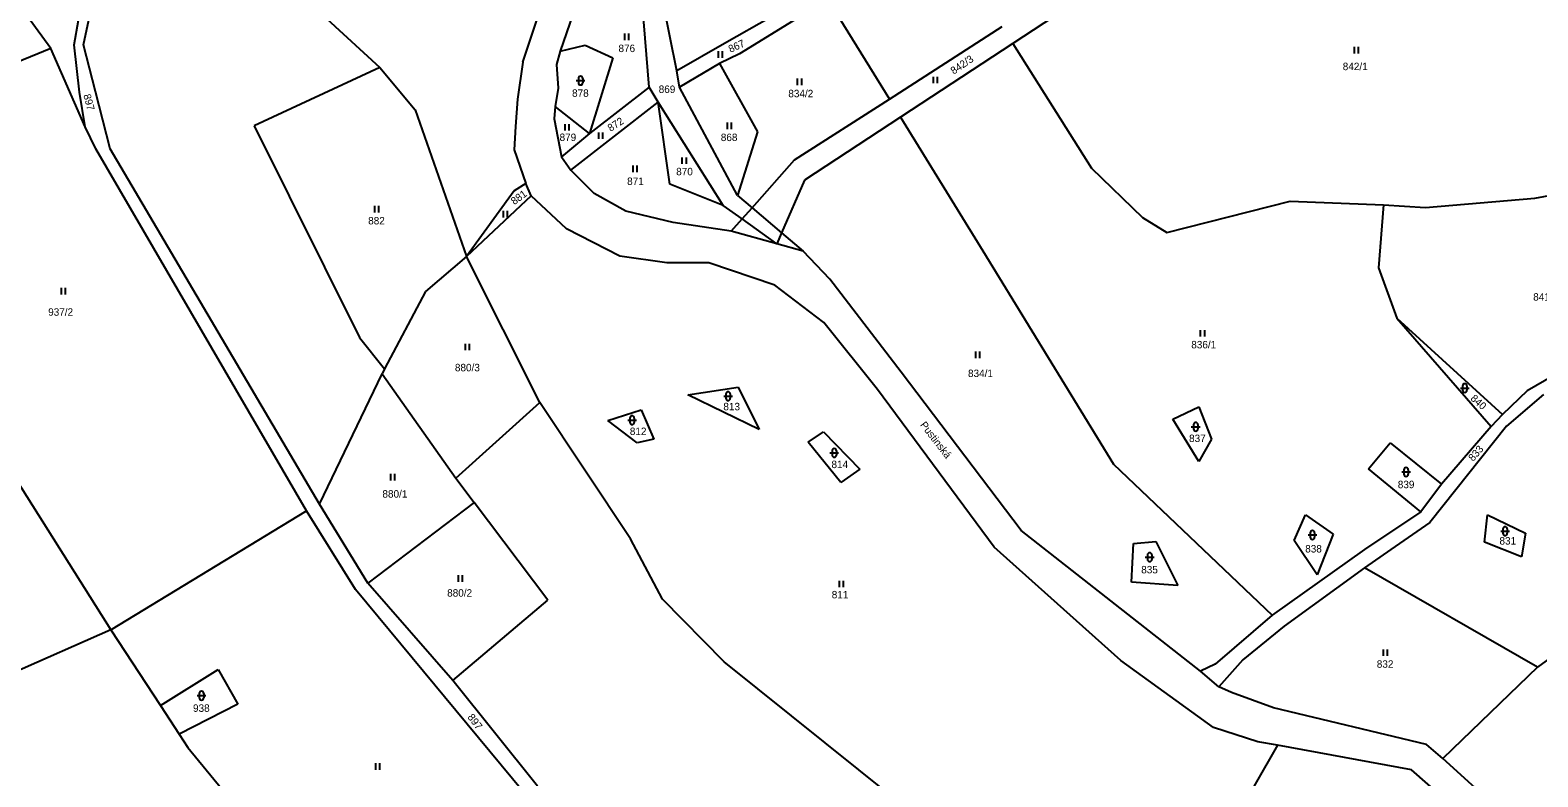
# Model space of a CAD drawing. Extents: x -670359 to -668019, y -978807 to -976674.
# Drawn here: x -669351.9 to -669008.2, y -977790.2 to -977619.9 of the extents above; entities that cross this region are included whole.
import ezdxf

# ---------------------------------------------------------------- set-up
doc = ezdxf.new("R2010")
doc.units = 0
for name, color, linetype in [('Hranice parcel', 7, 'Continuous'), ('Parcelní čísla', 7, 'Continuous'), ('Pop  PČ popisy', 7, 'Continuous'), ('Vnitřní kresba', 7, 'Continuous'), ('Značky kultur', 7, 'Continuous')]:
    doc.layers.add(name, color=color, linetype=linetype)

msp = doc.modelspace()

# ---------------------------------------------------------------- linework, layer by layer
at = {"layer": 'Hranice parcel'}
for p, q in [((-669333.55, -977756.65), (-669288.94, -977729.56)), ((-668975.51, -977835.05), (-669029.85, -977786.03))]:
    msp.add_line(p, q, dxfattribs=at)
for points in [[(-669239.62, -977627.27), (-669226.78, -977588.58)], [(-669347.25, -977624.1), (-669368.28, -977595.3)], [(-669341.89, -977623.27), (-669336.93, -977595.11)], [(-669339.81, -977623.26), (-669333.65, -977594.37)], [(-669225.3, -977607.95), (-669231.13, -977624.73)], [(-669172.23, -977610.73), (-669193.64, -977623)], [(-669104.24, -977607.4), (-669127.9, -977622.95)], [(-669204.48, -977629.2), (-669207.71, -977613.43)], [(-669170.07, -977612.9), (-669190.21, -977625.32)], [(-669170.07, -977612.9), (-669156.04, -977635.66)], [(-669284.27, -977617.33), (-669272.21, -977628.45)], [(-669210.82, -977632.95), (-669212.35, -977614.3)], [(-669156.04, -977635.66), (-669130.3, -977619.14)], [(-669347.25, -977624.1), (-669376.39, -977636.02)], [(-669339.39, -977641.96), (-669347.25, -977624.1)], [(-669340.72, -977634.05), (-669341.89, -977623.27)], [(-669337.04, -977633.95), (-669339.81, -977623.26)], [(-669231.13, -977624.73), (-669225.36, -977623.39)], [(-669225.36, -977623.39), (-669219.12, -977626.28)], [(-669193.64, -977623), (-669204.48, -977629.2)], [(-669127.9, -977622.95), (-669153.5, -977639.77)], [(-669127.9, -977622.95), (-669109.97, -977651.44)], [(-669239.62, -977627.27), (-669240.85, -977635.66)], [(-669231.13, -977624.73), (-669231.94, -977627.77)], [(-669231.94, -977627.77), (-669231.55, -977633.13)], [(-669219.12, -977626.28), (-669224.38, -977643.47)], [(-669194.78, -977627.55), (-669203.85, -977632.97)], [(-669190.21, -977625.32), (-669194.78, -977627.55)], [(-669194.78, -977627.55), (-669186.11, -977643.1)], [(-669272.21, -977628.45), (-669300.85, -977641.73)], [(-669272.21, -977628.45), (-669264.16, -977638.07)], [(-669203.85, -977632.97), (-669204.48, -977629.2)], [(-669339.39, -977641.96), (-669340.72, -977634.05)], [(-669333.69, -977646.96), (-669337.04, -977633.95)], [(-669231.55, -977633.13), (-669232.21, -977637.37)], [(-669210.82, -977632.95), (-669224.38, -977643.47)], [(-669208.75, -977636.39), (-669210.82, -977632.95)], [(-669190.64, -977657.65), (-669203.85, -977632.97)], [(-669264.16, -977638.07), (-669252.47, -977671.57)], [(-669240.85, -977635.66), (-669241.27, -977641.9)], [(-669232.21, -977637.37), (-669232.46, -977640.17)], [(-669224.38, -977643.47), (-669232.21, -977637.37)], [(-669228.65, -977651.83), (-669208.75, -977636.39)], [(-669193.93, -977659.88), (-669208.75, -977636.39)], [(-669206.09, -977655.04), (-669208.75, -977636.39)], [(-669177.64, -977649.52), (-669156.04, -977635.66)], [(-669232.46, -977640.17), (-669230.81, -977648.81)], [(-669153.5, -977639.77), (-669175.42, -977654.17)], [(-669153.5, -977639.77), (-669134.7, -977670.26)], [(-669336.97, -977646.98), (-669339.39, -977641.96)], [(-669300.85, -977641.73), (-669276.84, -977690.01)], [(-669241.27, -977641.9), (-669241.61, -977647.26)], [(-669224.38, -977643.47), (-669230.81, -977648.81)], [(-669186.11, -977643.1), (-669190.64, -977657.65)], [(-669288.94, -977729.56), (-669336.97, -977646.98)], [(-669285.99, -977728.02), (-669333.69, -977646.96)], [(-669241.61, -977647.26), (-669238.9, -977654.9)], [(-669230.81, -977648.81), (-669228.65, -977651.83)], [(-669223.38, -977657.2), (-669228.65, -977651.83)], [(-669187.35, -977660.43), (-669177.64, -977649.52)], [(-669109.97, -977651.44), (-669098.31, -977662.68)], [(-669238.9, -977654.9), (-669241.56, -977656.54)], [(-669237.72, -977657.72), (-669238.9, -977654.9)], [(-669193.93, -977659.88), (-669206.09, -977655.04)], [(-669175.42, -977654.17), (-669180.6, -977666.15)], [(-669008.85, -977658.21), (-668982.97, -977653.48)], [(-669241.56, -977656.54), (-669252.47, -977671.57)], [(-669237.72, -977657.72), (-669252.47, -977671.57)], [(-669229.65, -977665.27), (-669237.72, -977657.72)], [(-669216.11, -977661.23), (-669223.38, -977657.2)], [(-669190.64, -977657.65), (-669187.35, -977660.43)], [(-669033.84, -977660.38), (-669008.85, -977658.21)], [(-669205.31, -977663.82), (-669216.11, -977661.23)], [(-669189.62, -977662.98), (-669193.93, -977659.88)], [(-669187.35, -977660.43), (-669180.6, -977666.15)], [(-669092.8, -977666.06), (-669064.67, -977658.93)], [(-669064.67, -977658.93), (-669043.37, -977659.79)], [(-669043.37, -977659.79), (-669044.54, -977674.11)], [(-669043.37, -977659.79), (-669033.84, -977660.38)], [(-669217.5, -977671.46), (-669229.65, -977665.27)], [(-669192.1, -977665.77), (-669205.31, -977663.82)], [(-669181.7, -977668.68), (-669192.1, -977665.77)], [(-669181.7, -977668.68), (-669189.62, -977662.98)], [(-669098.31, -977662.68), (-669092.8, -977666.06)], [(-669175.7, -977670.3), (-669181.7, -977668.68)], [(-669180.6, -977666.15), (-669175.7, -977670.3)], [(-669252.47, -977671.57), (-669261.78, -977679.53)], [(-669235.71, -977704.86), (-669252.47, -977671.57)], [(-669206.78, -977673.01), (-669217.5, -977671.46)], [(-669169.63, -977676.72), (-669175.7, -977670.3)], [(-669134.7, -977670.26), (-669104.91, -977718.92)], [(-669197.17, -977672.96), (-669206.78, -977673.01)], [(-669182.13, -977678.05), (-669197.17, -977672.96)], [(-669044.54, -977674.11), (-669040.33, -977685.57)], [(-668965.02, -977675.86), (-669010.6, -977702.14)], [(-669170.95, -977686.56), (-669182.13, -977678.05)], [(-669153.37, -977697.89), (-669169.63, -977676.72)], [(-669261.78, -977679.53), (-669271.12, -977697.17)], [(-669040.33, -977685.57), (-669018.87, -977710.28)], [(-669040.33, -977685.57), (-669016.22, -977707.56)], [(-669158.74, -977701.88), (-669170.95, -977686.56)], [(-669276.84, -977690.01), (-669271.12, -977697.17)], [(-669285.99, -977728.02), (-669271.66, -977698.29)], [(-669271.12, -977697.17), (-669271.66, -977698.29)], [(-669271.66, -977698.29), (-669254.91, -977722.08)], [(-669126.02, -977733.98), (-669153.37, -977697.89)], [(-669201.99, -977703.12), (-669190.53, -977701.31)], [(-669185.76, -977711.01), (-669201.99, -977703.12)], [(-669190.53, -977701.31), (-669185.76, -977711.01)], [(-669132.12, -977737.81), (-669158.74, -977701.88)], [(-669010.6, -977702.14), (-669016.22, -977707.56)], [(-669006.92, -977703.03), (-669015.35, -977710.21)], [(-669254.91, -977722.08), (-669235.71, -977704.86)], [(-669215.07, -977735.89), (-669235.71, -977704.86)], [(-669220.19, -977708.91), (-669212.65, -977706.53)], [(-669212.65, -977706.53), (-669209.71, -977713.18)], [(-669091.42, -977708.63), (-669085.48, -977705.85)], [(-669085.48, -977705.85), (-669082.63, -977713.22)], [(-669213.56, -977714.05), (-669220.19, -977708.91)], [(-669085.52, -977718.25), (-669091.42, -977708.63)], [(-669015.35, -977710.21), (-669032.8, -977732.16)], [(-669018.87, -977710.28), (-669030.13, -977723.45)], [(-669016.22, -977707.56), (-669018.87, -977710.28)], [(-669361.08, -977713.13), (-669333.55, -977756.65)], [(-669209.71, -977713.18), (-669213.56, -977714.05)], [(-669174.56, -977713.84), (-669171.03, -977711.53)], [(-669167.14, -977723.06), (-669174.56, -977713.84)], [(-669171.03, -977711.53), (-669162.81, -977720.03)], [(-669082.63, -977713.22), (-669085.52, -977718.25)], [(-669046.77, -977719.96), (-669041.87, -977714.05)], [(-669041.87, -977714.05), (-669030.13, -977723.45)], [(-669162.81, -977720.03), (-669167.14, -977723.06)], [(-669104.91, -977718.92), (-669068.74, -977753.35)], [(-669034.87, -977729.76), (-669046.77, -977719.96)], [(-669254.91, -977722.08), (-669250.7, -977727.66)], [(-669030.13, -977723.45), (-669034.87, -977729.76)], [(-669277.73, -977747.47), (-669288.94, -977729.56)], [(-669274.94, -977746.02), (-669285.99, -977728.02)], [(-669250.7, -977727.66), (-669274.94, -977746.02)], [(-669233.89, -977749.93), (-669250.7, -977727.66)], [(-669063.72, -977736.32), (-669061.14, -977730.48)], [(-669061.14, -977730.48), (-669054.83, -977734.82)], [(-669034.87, -977729.76), (-669047.71, -977738.36)], [(-669020.37, -977736.69), (-669019.7, -977730.45)], [(-669019.7, -977730.45), (-669010.99, -977734.63)], [(-669085.12, -977766.11), (-669126.02, -977733.98)], [(-669032.8, -977732.16), (-669041.71, -977738.38)], [(-669207.75, -977749.67), (-669215.07, -977735.89)], [(-669103.29, -977763.65), (-669132.12, -977737.81)], [(-669100.83, -977745.82), (-669100.4, -977737.01)], [(-669100.4, -977737.01), (-669095.28, -977736.55)], [(-669095.28, -977736.55), (-669090.26, -977746.57)], [(-669058.54, -977744.1), (-669063.72, -977736.32)], [(-669054.83, -977734.82), (-669058.54, -977744.1)], [(-669011.89, -977739.99), (-669020.37, -977736.69)], [(-669010.99, -977734.63), (-669011.89, -977739.99)], [(-669047.71, -977738.36), (-669068.74, -977753.35)], [(-669041.71, -977738.38), (-669047.73, -977742.53)], [(-669047.73, -977742.53), (-669066.03, -977755.84)], [(-669008.24, -977765.2), (-669047.73, -977742.53)], [(-669239.37, -977793.76), (-669277.73, -977747.47)], [(-669255.54, -977768.2), (-669274.94, -977746.02)], [(-669090.26, -977746.57), (-669100.83, -977745.82)], [(-669255.54, -977768.2), (-669233.89, -977749.93)], [(-669193.7, -977763.96), (-669207.75, -977749.67)], [(-669068.74, -977753.35), (-669081.75, -977764.52)], [(-669333.55, -977756.65), (-669379.05, -977776.69)], [(-669333.55, -977756.65), (-669322.21, -977773.93)], [(-669066.03, -977755.84), (-669075.42, -977763.49)], [(-669155.29, -977794.72), (-669193.7, -977763.96)], [(-669082.12, -977778.92), (-669103.29, -977763.65)], [(-669081.75, -977764.52), (-669085.12, -977766.11)], [(-669075.42, -977763.49), (-669080.89, -977769.64)], [(-669008.24, -977765.2), (-669029.85, -977786.03)], [(-669004.63, -977762.49), (-669008.24, -977765.2)], [(-669322.21, -977773.93), (-669309.06, -977765.72)], [(-669309.06, -977765.72), (-669304.62, -977773.61)], [(-669236.24, -977792.33), (-669255.54, -977768.2)], [(-669080.89, -977769.64), (-669085.12, -977766.11)], [(-669078.01, -977770.93), (-669080.89, -977769.64)], [(-669068.49, -977774.48), (-669078.01, -977770.93)], [(-669322.21, -977773.93), (-669317.96, -977780.42)], [(-669304.62, -977773.61), (-669317.96, -977780.42)], [(-669033.61, -977782.82), (-669068.49, -977774.48)], [(-669072.04, -977782.23), (-669082.12, -977778.92)], [(-669317.96, -977780.42), (-669315.98, -977783.46)], [(-669067.56, -977782.96), (-669072.04, -977782.23)], [(-669315.98, -977783.46), (-669291.93, -977812.85)], [(-669067.56, -977782.96), (-669091.81, -977825.3)], [(-669036.99, -977788.57), (-669067.56, -977782.96)], [(-669029.85, -977786.03), (-669033.61, -977782.82)], [(-669015.27, -977807.68), (-669036.99, -977788.57)]]:
    msp.add_lwpolyline(points, dxfattribs=at)
at = {"layer": 'Vnitřní kresba'}
for points in [[(-669189.62, -977662.98), (-669187.35, -977660.43)], [(-669192.1, -977665.77), (-669189.62, -977662.98)], [(-669180.6, -977666.15), (-669181.7, -977668.68)]]:
    msp.add_lwpolyline(points, dxfattribs=at)
at = {"layer": 'Značky kultur'}
for p, q in [((-669216.41, -977620.74), (-669216.41, -977622.24)), ((-669215.41, -977622.24), (-669215.41, -977620.74)), ((-669050.06, -977623.73), (-669050.06, -977625.23)), ((-669049.06, -977625.23), (-669049.06, -977623.73)), ((-669195.06, -977624.73), (-669195.06, -977626.23)), ((-669194.06, -977626.23), (-669194.06, -977624.73)), ((-669226.95, -977630.94), (-669226.95, -977631.94)), ((-669225.95, -977630.94), (-669225.95, -977631.94)), ((-669177.03, -977630.97), (-669177.03, -977632.47)), ((-669176.03, -977632.47), (-669176.03, -977630.97)), ((-669146.04, -977630.56), (-669146.04, -977632.06)), ((-669145.04, -977632.06), (-669145.04, -977630.56)), ((-669227.45, -977631.44), (-669225.45, -977631.44)), ((-669230.05, -977641.35), (-669230.05, -977642.85)), ((-669229.05, -977642.85), (-669229.05, -977641.35)), ((-669193.04, -977641.03), (-669193.04, -977642.53)), ((-669192.04, -977642.53), (-669192.04, -977641.03)), ((-669222.36, -977643.25), (-669222.36, -977644.75)), ((-669221.36, -977644.75), (-669221.36, -977643.25)), ((-669214.51, -977650.83), (-669214.51, -977652.33)), ((-669213.51, -977652.33), (-669213.51, -977650.83)), ((-669203.32, -977648.95), (-669203.32, -977650.45)), ((-669202.32, -977650.45), (-669202.32, -977648.95)), ((-669273.44, -977660.03), (-669273.44, -977661.53)), ((-669272.44, -977661.53), (-669272.44, -977660.03)), ((-669244.12, -977661.13), (-669244.12, -977662.63)), ((-669243.12, -977662.63), (-669243.12, -977661.13)), ((-669344.9, -977678.68), (-669344.9, -977680.18)), ((-669343.9, -977680.18), (-669343.9, -977678.68)), ((-669085.15, -977688.32), (-669085.15, -977689.82)), ((-669084.15, -977689.82), (-669084.15, -977688.32)), ((-669252.74, -977691.42), (-669252.74, -977692.92)), ((-669251.74, -977692.92), (-669251.74, -977691.42)), ((-669136.38, -977693.23), (-669136.38, -977694.73)), ((-669135.38, -977694.73), (-669135.38, -977693.23)), ((-669193.81, -977703.38), (-669191.81, -977703.38)), ((-669193.31, -977702.88), (-669193.31, -977703.88)), ((-669192.31, -977702.88), (-669192.31, -977703.88)), ((-669025.85, -977701.54), (-669023.85, -977701.54)), ((-669025.35, -977701.04), (-669025.35, -977702.04)), ((-669024.35, -977701.04), (-669024.35, -977702.04)), ((-669215.69, -977708.87), (-669213.69, -977708.87)), ((-669215.19, -977708.37), (-669215.19, -977709.37)), ((-669214.19, -977708.37), (-669214.19, -977709.37)), ((-669087.2, -977710.36), (-669085.2, -977710.36)), ((-669086.7, -977709.86), (-669086.7, -977710.86)), ((-669085.7, -977709.86), (-669085.7, -977710.86)), ((-669169.61, -977716.32), (-669167.61, -977716.32)), ((-669169.11, -977715.82), (-669169.11, -977716.82)), ((-669168.11, -977715.82), (-669168.11, -977716.82)), ((-669039.23, -977720.67), (-669037.23, -977720.67)), ((-669038.73, -977720.17), (-669038.73, -977721.17)), ((-669037.73, -977720.17), (-669037.73, -977721.17)), ((-669269.81, -977721.11), (-669269.81, -977722.61)), ((-669268.81, -977722.61), (-669268.81, -977721.11)), ((-669016.65, -977734.16), (-669014.65, -977734.16)), ((-669016.15, -977733.66), (-669016.15, -977734.66)), ((-669015.15, -977733.66), (-669015.15, -977734.66)), ((-669060.58, -977735.04), (-669058.58, -977735.04)), ((-669060.08, -977734.54), (-669060.08, -977735.54)), ((-669059.08, -977734.54), (-669059.08, -977735.54)), ((-669097.69, -977740.09), (-669095.69, -977740.09)), ((-669097.19, -977739.59), (-669097.19, -977740.59)), ((-669096.19, -977739.59), (-669096.19, -977740.59)), ((-669254.34, -977744.23), (-669254.34, -977745.73)), ((-669253.34, -977745.73), (-669253.34, -977744.23)), ((-669167.51, -977745.47), (-669167.51, -977746.97)), ((-669166.51, -977746.97), (-669166.51, -977745.47)), ((-669043.48, -977761.11), (-669043.48, -977762.61)), ((-669042.48, -977762.61), (-669042.48, -977761.11)), ((-669313.87, -977771.66), (-669311.87, -977771.66)), ((-669313.37, -977771.16), (-669313.37, -977772.16)), ((-669312.37, -977771.16), (-669312.37, -977772.16)), ((-669273.22, -977787.09), (-669273.22, -977788.59)), ((-669272.22, -977788.59), (-669272.22, -977787.09))]:
    msp.add_line(p, q, dxfattribs=at)
for centre, start, end in [((-669226.45, -977630.94), 0, 180), ((-669226.45, -977631.94), 180, 0), ((-669192.81, -977702.88), 0, 180), ((-669024.85, -977701.04), 0, 180), ((-669024.85, -977702.04), 180, 0), ((-669192.81, -977703.88), 180, 0), ((-669214.69, -977708.37), 0, 180), ((-669214.69, -977709.37), 180, 0), ((-669086.2, -977709.86), 0, 180), ((-669086.2, -977710.86), 180, 0), ((-669168.61, -977715.82), 0, 180), ((-669168.61, -977716.82), 180, 0), ((-669038.23, -977720.17), 0, 180), ((-669038.23, -977721.17), 180, 0), ((-669059.58, -977734.54), 0, 180), ((-669015.65, -977733.66), 0, 180), ((-669059.58, -977735.54), 180, 0), ((-669015.65, -977734.66), 180, 0), ((-669096.69, -977739.59), 0, 180), ((-669096.69, -977740.59), 180, 0), ((-669312.87, -977771.16), 0, 180), ((-669312.87, -977772.16), 180, 0)]:
    msp.add_arc(centre, 0.5, start, end, dxfattribs=at)

# ---------------------------------------------------------------- texts
at = {"layer": 'Parcelní čísla'}
for s, p in [('876', (-669217.8, -977624.94)), ('842/1', (-669052.67, -977629.06)), ('878', (-669228.38, -977635.14)), ('869', (-669208.63, -977634.26)), ('834/2', (-669179.08, -977635.24)), ('879', (-669231.23, -977645.22)), ('868', (-669194.47, -977645.23)), ('870', (-669204.64, -977653.03)), ('871', (-669215.83, -977655.24)), ('882', (-669274.87, -977664.23)), ('841', (-669009.25, -977681.61)), ('937/2', (-669347.83, -977685.05)), ('836/1', (-669087.21, -977692.49)), ('880/3', (-669255.09, -977697.72)), ('834/1', (-669138.11, -977699.03)), ('813', (-669193.89, -977706.61)), ('812', (-669215.21, -977712.25)), ('837', (-669087.71, -977713.85)), ('814', (-669169.24, -977719.79)), ('839', (-669040.12, -977724.37)), ('880/1', (-669271.62, -977726.52)), ('838', (-669061.23, -977739.03)), ('831', (-669016.94, -977737.22)), ('835', (-669098.62, -977743.79)), ('880/2', (-669256.86, -977749.1)), ('811', (-669169.18, -977749.49)), ('832', (-669044.91, -977765.31)), ('938', (-669314.8, -977775.36))]:
    msp.add_text(s, height=1.7, dxfattribs=at).set_placement(p)
for s, rotation, p in [('867', 24.5377, (-669192.27, -977625.13)), ('842/3', 34.1475, (-669141.38, -977630.11)), ('897', 285.2966, (-669339.83, -977634.75)), ('872', 32.7935, (-669219.6, -977643.16)), ('881', 36.5525, (-669241.54, -977659.86)), ('840', 318.3109, (-669023.68, -977704.11)), ('833', 48.7314, (-669022.94, -977718.38)), ('897', 307.2857, (-669252.32, -977776.6))]:
    msp.add_text(s, height=1.7, rotation=rotation, dxfattribs=at).set_placement(p)
at = {"layer": 'Pop  PČ popisy'}
msp.add_text('Pustinská', height=1.7, rotation=307.7872, dxfattribs=at).set_placement((-669149.13, -977709.98))

doc.saveas('drawing.dxf')
